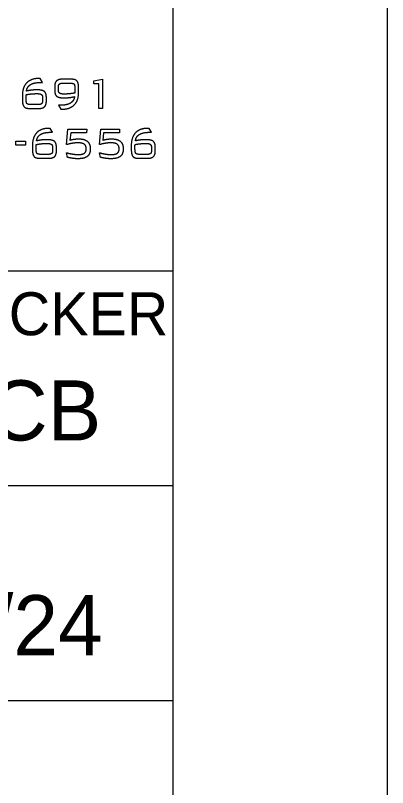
# Model space of a CAD drawing. Extents: x 0 to 680, y -49 to 440.
# Drawn here: x 662.66 to 680, y 35.94 to 71.89 of the extents above; entities that cross this region are included whole.
import ezdxf

# ---------------------------------------------------------------- set-up
doc = ezdxf.new("R2010")
doc.units = 0
for name, color, linetype in [('SV_X_Shot_Marker', 7, 'Continuous'), ('UT_X_Misc_Cells', 7, 'Continuous'), ('UT_X_Telecom_Cells', 7, 'Continuous'), ('VG_X_Cells', 7, 'Continuous')]:
    doc.layers.add(name, color=color, linetype=linetype)

msp = doc.modelspace()

# ---------------------------------------------------------------- linework, layer by layer
at = {"layer": 'SV_X_Shot_Marker'}
for p, q in [((640, 60), (670, 60)), ((640, 50), (670, 50)), ((640, 40), (670, 40))]:
    msp.add_line(p, q, dxfattribs=at)
msp.add_lwpolyline([(30, 430), (670, 430), (670, 10), (30, 10)], close=True, dxfattribs=at)
at = {"layer": 'UT_X_Telecom_Cells'}
for p, q in [((663.922, 68.767), (663.811, 68.945)), ((665.27, 68.917), (664.84, 68.917)), ((664.876, 68.734), (665.207, 68.734)), ((664.49, 68.585), (664.49, 68.402)), ((664.663, 68.437), (664.663, 68.525)), ((665.607, 68.319), (665.607, 68.498)), ((662.985, 68.155), (662.985, 67.976)), ((663.162, 68.197), (663.162, 68.197)), ((663.927, 68.036), (663.927, 67.949)), ((664.102, 67.888), (664.102, 68.072)), ((665.428, 68.276), (665.428, 68.276)), ((663.716, 67.738), (663.385, 67.738)), ((664.669, 67.709), (664.78, 67.528)), ((663.319, 67.556), (663.752, 67.556)), ((664.391, 66.447), (664.28, 66.625)), ((668.996, 66.447), (668.885, 66.625)), ((663.454, 65.835), (663.454, 65.656)), ((663.631, 65.877), (663.631, 65.877)), ((668.059, 65.835), (668.059, 65.656)), ((668.236, 65.877), (668.236, 65.877)), ((664.185, 65.418), (663.854, 65.418)), ((664.396, 65.716), (664.396, 65.629)), ((664.571, 65.568), (664.571, 65.752)), ((665.094, 65.28), (665.041, 65.498)), ((666.629, 65.28), (666.576, 65.498)), ((668.79, 65.418), (668.459, 65.418)), ((669.001, 65.716), (669.001, 65.629)), ((669.176, 65.568), (669.176, 65.752)), ((663.788, 65.237), (664.221, 65.237)), ((668.393, 65.237), (668.826, 65.237))]:
    msp.add_line(p, q, dxfattribs=at)
for points in [[(666.551, 67.556), (666.551, 68.703), (666.313, 68.703), (666.313, 68.839), (666.717, 68.926), (666.717, 67.556)], [(662.673, 65.843), (662.673, 66.036), (663.133, 66.036), (663.133, 65.843)]]:
    msp.add_lwpolyline(points, close=True, dxfattribs=at)
for points in [[(665.044, 65.872), (665.1, 66.597), (665.981, 66.597), (665.969, 66.415), (665.237, 66.415), (665.199, 66.084)], [(666.579, 65.872), (666.635, 66.597), (667.516, 66.597), (667.504, 66.415), (666.772, 66.415), (666.734, 66.084)]]:
    msp.add_lwpolyline(points, dxfattribs=at)
for points in [[(663.181, 68.743), (662.985, 68.535), (662.985, 68.155)], [(663.178, 68.365), (663.202, 68.571), (663.368, 68.67)], [(663.738, 68.951), (663.378, 68.951), (663.181, 68.743)], [(663.368, 68.67), (663.535, 68.769), (663.855, 68.769)], [(663.768, 68.95), (663.752, 68.951), (663.738, 68.951)], [(663.811, 68.945), (663.784, 68.949), (663.768, 68.95)], [(663.855, 68.769), (663.881, 68.769), (663.896, 68.769)], [(663.896, 68.769), (663.911, 68.768), (663.922, 68.767)], [(664.575, 68.836), (664.49, 68.755), (664.49, 68.585)], [(664.84, 68.917), (664.66, 68.917), (664.575, 68.836)], [(664.663, 68.525), (664.663, 68.648), (664.706, 68.691)], [(664.706, 68.691), (664.749, 68.734), (664.876, 68.734)], [(665.207, 68.734), (665.366, 68.734), (665.4, 68.685)], [(665.536, 68.828), (665.464, 68.917), (665.27, 68.917)], [(665.4, 68.685), (665.434, 68.635), (665.434, 68.361)], [(665.607, 68.498), (665.607, 68.738), (665.536, 68.828)], [(663.416, 68.408), (663.296, 68.394), (663.178, 68.365)], [(663.661, 68.423), (663.537, 68.423), (663.416, 68.408)], [(664.008, 68.347), (663.915, 68.423), (663.661, 68.423)], [(664.102, 68.072), (664.102, 68.27), (664.008, 68.347)], [(664.49, 68.402), (664.49, 68.204), (664.583, 68.127)], [(664.716, 68.27), (664.663, 68.314), (664.663, 68.437)], [(665.41, 67.732), (665.607, 67.939), (665.607, 68.319)], [(665.433, 68.323), (665.431, 68.301), (665.428, 68.276)], [(665.434, 68.361), (665.434, 68.344), (665.433, 68.323)], [(662.985, 67.976), (662.985, 67.735), (663.056, 67.646)], [(663.154, 68.115), (663.154, 68.13), (663.156, 68.151)], [(663.19, 67.79), (663.154, 67.842), (663.154, 68.115)], [(663.156, 68.151), (663.158, 68.171), (663.162, 68.197)], [(663.162, 68.197), (663.276, 68.222), (663.404, 68.235)], [(663.404, 68.235), (663.532, 68.247), (663.67, 68.247)], [(663.67, 68.247), (663.82, 68.247), (663.874, 68.204)], [(663.874, 68.204), (663.927, 68.16), (663.927, 68.036)], [(663.927, 67.949), (663.927, 67.825), (663.884, 67.781)], [(664.583, 68.127), (664.677, 68.05), (664.929, 68.05)], [(664.92, 68.226), (664.77, 68.226), (664.716, 68.27)], [(665.186, 68.239), (665.058, 68.226), (664.92, 68.226)], [(664.929, 68.05), (665.053, 68.05), (665.175, 68.065)], [(665.175, 68.065), (665.296, 68.08), (665.414, 68.108)], [(665.428, 68.276), (665.314, 68.252), (665.186, 68.239)], [(665.414, 68.108), (665.39, 67.903), (665.223, 67.803)], [(663.056, 67.646), (663.127, 67.556), (663.319, 67.556)], [(663.385, 67.738), (663.225, 67.738), (663.19, 67.79)], [(663.884, 67.781), (663.842, 67.738), (663.716, 67.738)], [(663.752, 67.556), (663.932, 67.556), (664.017, 67.637)], [(664.017, 67.637), (664.102, 67.717), (664.102, 67.888)], [(664.68, 67.708), (664.673, 67.708), (664.669, 67.709)], [(664.734, 67.704), (664.717, 67.704), (664.68, 67.708)], [(665.223, 67.803), (665.055, 67.704), (664.734, 67.704)], [(664.854, 67.524), (665.214, 67.524), (665.41, 67.732)], [(664.78, 67.528), (664.793, 67.525), (664.808, 67.525)], [(664.808, 67.525), (664.823, 67.524), (664.854, 67.524)], [(664.207, 66.631), (663.847, 66.631), (663.651, 66.423)], [(664.237, 66.63), (664.221, 66.631), (664.207, 66.631)], [(664.28, 66.625), (664.253, 66.629), (664.237, 66.63)], [(668.812, 66.631), (668.452, 66.631), (668.256, 66.423)], [(668.842, 66.63), (668.826, 66.631), (668.812, 66.631)], [(668.885, 66.625), (668.858, 66.629), (668.842, 66.63)], [(663.651, 66.423), (663.454, 66.215), (663.454, 65.835)], [(663.647, 66.046), (663.671, 66.251), (663.837, 66.35)], [(663.837, 66.35), (664.004, 66.449), (664.324, 66.449)], [(664.324, 66.449), (664.35, 66.449), (664.365, 66.449)], [(664.365, 66.449), (664.38, 66.448), (664.391, 66.447)], [(665.401, 66.126), (665.502, 66.14), (665.602, 66.14)], [(665.602, 66.14), (665.88, 66.14), (666.014, 66.026)], [(666.936, 66.126), (667.037, 66.14), (667.137, 66.14)], [(667.137, 66.14), (667.415, 66.14), (667.549, 66.026)], [(668.256, 66.423), (668.059, 66.215), (668.059, 65.835)], [(668.252, 66.046), (668.276, 66.251), (668.442, 66.35)], [(668.442, 66.35), (668.609, 66.449), (668.929, 66.449)], [(668.929, 66.449), (668.955, 66.449), (668.97, 66.449)], [(668.97, 66.449), (668.985, 66.448), (668.996, 66.447)], [(663.623, 65.795), (663.623, 65.81), (663.626, 65.831)], [(663.659, 65.47), (663.623, 65.522), (663.623, 65.795)], [(663.626, 65.831), (663.628, 65.852), (663.631, 65.877)], [(663.631, 65.877), (663.745, 65.902), (663.873, 65.915)], [(663.885, 66.089), (663.765, 66.074), (663.647, 66.046)], [(663.873, 65.915), (664.001, 65.928), (664.139, 65.928)], [(664.13, 66.103), (664.006, 66.103), (663.885, 66.089)], [(664.478, 66.027), (664.384, 66.103), (664.13, 66.103)], [(664.139, 65.928), (664.289, 65.928), (664.343, 65.884)], [(664.343, 65.884), (664.396, 65.84), (664.396, 65.716)], [(664.571, 65.752), (664.571, 65.95), (664.478, 66.027)], [(665.323, 65.935), (665.191, 65.915), (665.044, 65.872)], [(665.199, 66.084), (665.301, 66.113), (665.401, 66.126)], [(665.579, 65.956), (665.456, 65.956), (665.323, 65.935)], [(665.87, 65.89), (665.779, 65.956), (665.579, 65.956)], [(665.96, 65.677), (665.96, 65.823), (665.87, 65.89)], [(666.014, 66.026), (666.148, 65.912), (666.148, 65.674)], [(666.858, 65.935), (666.726, 65.915), (666.579, 65.872)], [(666.734, 66.084), (666.836, 66.113), (666.936, 66.126)], [(667.114, 65.956), (666.991, 65.956), (666.858, 65.935)], [(667.405, 65.89), (667.314, 65.956), (667.114, 65.956)], [(667.495, 65.677), (667.495, 65.823), (667.405, 65.89)], [(667.549, 66.026), (667.683, 65.912), (667.683, 65.674)], [(668.228, 65.795), (668.228, 65.81), (668.231, 65.831)], [(668.264, 65.47), (668.228, 65.522), (668.228, 65.795)], [(668.231, 65.831), (668.233, 65.852), (668.236, 65.877)], [(668.236, 65.877), (668.35, 65.902), (668.478, 65.915)], [(668.49, 66.089), (668.37, 66.074), (668.252, 66.046)], [(668.478, 65.915), (668.606, 65.928), (668.744, 65.928)], [(668.735, 66.103), (668.611, 66.103), (668.49, 66.089)], [(669.083, 66.027), (668.989, 66.103), (668.735, 66.103)], [(668.744, 65.928), (668.894, 65.928), (668.948, 65.884)], [(668.948, 65.884), (669.001, 65.84), (669.001, 65.716)], [(669.176, 65.752), (669.176, 65.95), (669.083, 66.027)], [(663.454, 65.656), (663.454, 65.415), (663.525, 65.326)], [(663.854, 65.418), (663.695, 65.418), (663.659, 65.47)], [(664.354, 65.461), (664.311, 65.418), (664.185, 65.418)], [(664.396, 65.629), (664.396, 65.505), (664.354, 65.461)], [(664.486, 65.317), (664.571, 65.397), (664.571, 65.568)], [(665.041, 65.498), (665.19, 65.455), (665.33, 65.433)], [(665.33, 65.433), (665.47, 65.411), (665.591, 65.411)], [(665.591, 65.411), (665.788, 65.411), (665.874, 65.473)], [(665.874, 65.473), (665.96, 65.536), (665.96, 65.677)], [(666.148, 65.674), (666.148, 65.431), (666.011, 65.324)], [(666.576, 65.498), (666.725, 65.455), (666.865, 65.433)], [(666.865, 65.433), (667.005, 65.411), (667.126, 65.411)], [(667.126, 65.411), (667.323, 65.411), (667.409, 65.473)], [(667.409, 65.473), (667.495, 65.536), (667.495, 65.677)], [(667.683, 65.674), (667.683, 65.431), (667.546, 65.324)], [(668.059, 65.656), (668.059, 65.415), (668.13, 65.326)], [(668.459, 65.418), (668.3, 65.418), (668.264, 65.47)], [(668.959, 65.461), (668.916, 65.418), (668.79, 65.418)], [(669.001, 65.629), (669.001, 65.505), (668.959, 65.461)], [(669.091, 65.317), (669.176, 65.397), (669.176, 65.568)], [(663.525, 65.326), (663.596, 65.237), (663.788, 65.237)], [(664.221, 65.237), (664.401, 65.237), (664.486, 65.317)], [(665.348, 65.231), (665.237, 65.246), (665.094, 65.28)], [(665.56, 65.216), (665.459, 65.216), (665.348, 65.231)], [(666.011, 65.324), (665.874, 65.216), (665.56, 65.216)], [(666.883, 65.231), (666.772, 65.246), (666.629, 65.28)], [(667.095, 65.216), (666.994, 65.216), (666.883, 65.231)], [(667.546, 65.324), (667.409, 65.216), (667.095, 65.216)], [(668.13, 65.326), (668.201, 65.237), (668.393, 65.237)], [(668.826, 65.237), (669.006, 65.237), (669.091, 65.317)]]:
    msp.add_open_spline(points, degree=2, dxfattribs=at)
at = {"layer": 'VG_X_Cells'}
msp.add_lwpolyline([(0, 0), (680, 0), (680, 440), (0, 440)], close=True, dxfattribs=at)

# ---------------------------------------------------------------- texts
at = {"layer": 'UT_X_Misc_Cells'}
for s, height, p in [('CHECKER', 2, (656.704, 57)), ('ACB', 2.8, (658.959, 52.1)), ('11/07/24', 2.8, (652.155, 42.1))]:
    msp.add_text(s, height=height, dxfattribs=at).set_placement(p)

doc.saveas('drawing.dxf')
